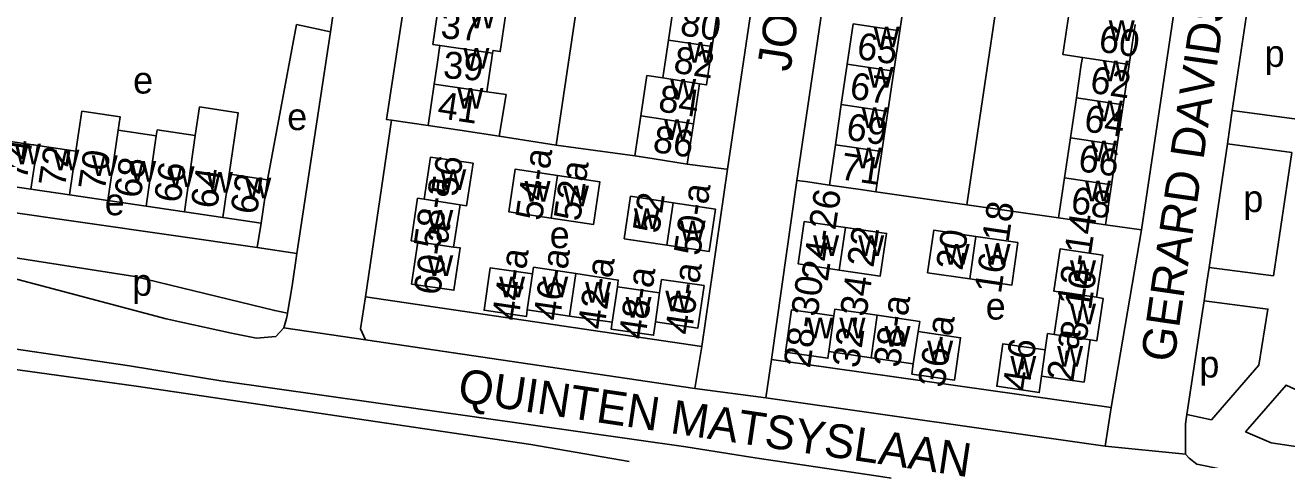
# Model space of a CAD drawing. Extents: x 163012 to 165277, y 382513 to 383987.
# Drawn here: x 163733.4 to 163920.9, y 382941.3 to 383005.9 of the extents above; entities that cross this region are included whole.
import ezdxf

# ---------------------------------------------------------------- set-up
doc = ezdxf.new("R2010")
doc.units = 0
for name, color, linetype in [('BLT_Basislijn', 7, 'Continuous'), ('BLT_Bebouwing', 7, 'Continuous'), ('BLT_Centroide', 7, 'Continuous'), ('BLT_Huisnummer', 7, 'Continuous'), ('BLT_Huisnummer_ tussenligend', 7, 'Continuous'), ('BLT_Huisnummer_reeks', 7, 'Continuous'), ('BLT_Onderverdeling_panden', 7, 'Continuous'), ('BLT_Straatnaam', 7, 'Continuous'), ('BLT_Vlakafsluiter', 7, 'Continuous')]:
    doc.layers.add(name, color=color, linetype=linetype)

msp = doc.modelspace()

# ---------------------------------------------------------------- linework, layer by layer
at = {"layer": 'BLT_Basislijn'}
for p, q in [((163769.45, 382982.9), (163773.76, 383005.95)), ((163773.76, 383005.95), (163778.82, 383004.9)), ((163773.8, 382971.94), (163778.82, 383004.9)), ((163912.83, 382993.19), (163922.44, 382991.91)), ((163787.87, 382991.74), (163783.98, 382965.47)), ((163793.29, 382990.97), (163787.87, 382991.74)), ((163812.36, 382988.05), (163803.88, 382989.36)), ((163912.1, 382988.25), (163921.69, 382986.96)), ((163824.01, 382986.42), (163812.36, 382988.05)), ((163837.27, 382984.52), (163831.82, 382985.23)), ((163837.81, 382984.44), (163833.99, 382958.09)), ((163844.33, 382956.18), (163848.1, 382982.79)), ((163852.97, 382982.1), (163849.41, 382982.61)), ((163873.4, 382979.16), (163859.87, 382981.08)), ((163887.01, 382977.21), (163873.4, 382979.16)), ((163728.05, 382978.52), (163767.9, 382972.83)), ((163767.9, 382972.83), (163768.5, 382976.45)), ((163899.33, 382975.42), (163893.98, 382976.17)), ((163894.85, 382949.03), (163899.33, 382975.42)), ((163767.9, 382972.83), (163773.8, 382971.94)), ((163773.1, 382967.11), (163773.8, 382971.94)), ((163783.98, 382965.47), (163833.99, 382958.09)), ((163908.32, 382962.66), (163906.07, 382948.01)), ((163783.99, 382959.1), (163832.93, 382951.88)), ((163832.93, 382951.88), (163833.99, 382958.09)), ((163844.33, 382956.18), (163843.49, 382950.45)), ((163844.33, 382956.18), (163894.85, 382949.03)), ((163762.51, 382952.99), (163831.62, 382943.18)), ((163843.49, 382950.45), (163893.93, 382943.26))]:
    msp.add_line(p, q, dxfattribs=at)
for points in [[(163788.12, 383067.75), (163788.07, 383067.4), (163778.82, 383004.9)], [(163848.86, 383058.88), (163837.81, 382984.44)], [(163787.87, 382991.74), (163787.1, 382991.85), (163795.88, 383049.14), (163795.92, 383049.43)], [(163910.31, 383048.96), (163910.2, 383048.25), (163899.33, 382975.42)], [(163812.36, 382988.05), (163820.82, 383045.09), (163820.88, 383045.5)], [(163848.1, 382982.79), (163855.33, 383031.73), (163855.5, 383032.85)], [(163880.83, 383029.32), (163880.66, 383028.19), (163873.4, 382979.16)], [(163915.17, 383009.03), (163912.83, 382993.19)], [(163912.83, 382993.19), (163912.1, 382988.25)], [(163912.1, 382988.25), (163909.38, 382969.84)], [(163921.69, 382986.96), (163918.94, 382968.59)], [(163837.81, 382984.44), (163837.27, 382984.52)], [(163849.41, 382982.61), (163848.1, 382982.79)], [(163772.42, 382963.06), (163770.5, 382963.43), (163749.69, 382968.5), (163729.4, 382971.68), (163728.79, 382971.24), (163728.38, 382969.07)], [(163909.38, 382969.84), (163909.06, 382967.67)], [(163909.38, 382969.84), (163918.94, 382968.59)], [(163754.38, 382962.23), (163739.99, 382966.02), (163728.92, 382968.95), (163728.38, 382969.07)], [(163909.06, 382967.67), (163908.65, 382964.89)], [(163772.42, 382963.06), (163773.1, 382967.11)], [(163783.98, 382965.47), (163783.27, 382960.75), (163783.99, 382959.1)], [(163908.65, 382964.89), (163908.32, 382962.66)], [(163908.65, 382964.89), (163918.14, 382963.65), (163916.78, 382955.31)], [(163754.38, 382962.23), (163764.09, 382960.07), (163767.78, 382959.35)], [(163767.78, 382959.35), (163770.66, 382959.57), (163771.84, 382960.86), (163772.28, 382962.24), (163772.36, 382962.72), (163772.42, 382963.06)], [(163709.47, 382952.17), (163709.84, 382953.93), (163710.03, 382954.74), (163710.48, 382955.7), (163711.05, 382956.5), (163711.99, 382957.35), (163713.32, 382958.03), (163714.74, 382958.61), (163716.43, 382959.04), (163718.05, 382959.31), (163721.95, 382959.17), (163748.93, 382955.25), (163762.51, 382952.99)], [(163703.62, 382829.62), (163715.3, 382907.82), (163715.86, 382924.36), (163716.41, 382929), (163717.21, 382932.64), (163717.47, 382936.2), (163717.23, 382939.86), (163716.47, 382943.53), (163715.71, 382947.3), (163716.39, 382948.99), (163718.15, 382950.51), (163719.84, 382952.44), (163721.19, 382954.28), (163722.24, 382956.02), (163749.89, 382952.18), (163808.55, 382943.55), (163823.2, 382940.98)], [(163916.78, 382955.31), (163909.76, 382947.2)], [(163968.8, 382943), (163956.77, 382943.99), (163943.83, 382945.66), (163933.59, 382947.74), (163922.89, 382951.43), (163920.84, 382952.36), (163914.82, 382945.41)], [(163893.93, 382943.26), (163894.85, 382949.03)], [(163905.86, 382945.2), (163905.86, 382946.61), (163906.07, 382948.01)], [(163906.07, 382948.01), (163909.76, 382947.2)], [(163905.9, 382942.08), (163905.86, 382945.2)], [(163914.82, 382945.41), (163918.6, 382943.79)], [(163831.62, 382943.18), (163841.26, 382941.65), (163842.56, 382941.46)], [(163918.6, 382943.79), (163957.28, 382937.97)], [(163842.56, 382941.46), (163860.91, 382938.73), (163862.14, 382938.55)], [(163911.24, 382939.84), (163907.55, 382940.63), (163906.43, 382941.52), (163905.9, 382942.08)]]:
    msp.add_lwpolyline(points, dxfattribs=at)
at = {"layer": 'BLT_Bebouwing'}
for p, q in [((163863.42, 383005.03), (163864.3, 383011.02)), ((163829.02, 383003.65), (163829.87, 383009.33)), ((163835.54, 383002.68), (163836.38, 383008.36)), ((163855.6, 383000.07), (163856.47, 383006.06)), ((163897.5, 383000.01), (163898.39, 383005.96)), ((163855.6, 383000.07), (163854.72, 382994.07)), ((163897.5, 383000.01), (163896.62, 382994.05)), ((163862.54, 382999.04), (163861.65, 382993.05)), ((163794.2, 382997.1), (163793.29, 382990.97)), ((163833.63, 382997.15), (163832.73, 382991.21)), ((163854.72, 382994.07), (163853.85, 382988.08)), ((163889.67, 382995.08), (163888.78, 382989.13)), ((163896.62, 382994.05), (163895.74, 382988.09)), ((163824.01, 382986.42), (163824.92, 382992.4)), ((163861.65, 382993.05), (163860.76, 382987.07)), ((163752.91, 382989.4), (163747.25, 382990.24)), ((163832.73, 382991.21), (163831.82, 382985.23)), ((163853.85, 382988.08), (163852.97, 382982.1)), ((163888.78, 382989.13), (163887.9, 382983.17)), ((163895.74, 382988.09), (163894.86, 382982.14)), ((163740.94, 382987.13), (163735.24, 382987.97)), ((163860.76, 382987.07), (163859.87, 382981.08)), ((163769.45, 382982.9), (163768.5, 382976.45)), ((163887.9, 382983.17), (163887.01, 382977.21)), ((163734.28, 382981.5), (163728.53, 382982.35)), ((163739.99, 382980.66), (163734.28, 382981.5)), ((163745.69, 382979.82), (163739.99, 382980.66)), ((163894.86, 382982.14), (163893.98, 382976.17)), ((163751.39, 382978.98), (163745.69, 382979.82)), ((163757.1, 382978.14), (163751.39, 382978.98)), ((163797.1, 382972.89), (163798.05, 382979.17)), ((163762.8, 382977.29), (163757.1, 382978.14)), ((163768.5, 382976.45), (163762.8, 382977.29)), ((163827.72, 382966.07), (163821.43, 382966.98)), ((163887.31, 382966.17), (163886.38, 382959.89)), ((163808.05, 382963.53), (163814.34, 382962.61)), ((163814.34, 382962.61), (163820.64, 382961.7)), ((163852.88, 382957.34), (163859.15, 382956.43)), ((163859.15, 382956.43), (163865.41, 382955.52))]:
    msp.add_line(p, q, dxfattribs=at)
for points in [[(163795.06, 383002.87), (163794.71, 383002.92), (163794.03, 383003.02), (163794.92, 383009.08)], [(163802.89, 383001.71), (163802.95, 383002.11), (163804.03, 383001.95), (163804.87, 383007.6)], [(163890.55, 383001.04), (163887.67, 383001.52), (163888.53, 383007.44)], [(163863.42, 383005.03), (163862.69, 383000), (163862.54, 382999.04)], [(163828.17, 382998.02), (163828.47, 383000), (163829.02, 383003.65)], [(163795.06, 383002.87), (163794.63, 383000), (163794.2, 382997.1)], [(163802.89, 383001.71), (163802.67, 383000.25), (163802.64, 383000), (163802.04, 382995.94)], [(163835.54, 383002.68), (163835.14, 383000), (163834.69, 382996.99), (163833.63, 382997.15)], [(163890.55, 383001.04), (163890.39, 383000), (163889.67, 382995.08)], [(163824.92, 382992.4), (163825.83, 382998.37), (163828.17, 382998.02)], [(163803.88, 382989.36), (163804.9, 382995.55), (163802.04, 382995.94)], [(163763.75, 382983.74), (163765.07, 382992.86), (163759.33, 382993.72), (163758.7, 382989.46)], [(163747.25, 382990.24), (163747.55, 382992.22), (163741.84, 382993.07), (163740.94, 382987.13)], [(163752.91, 382989.4), (163753.05, 382990.3), (163758.7, 382989.46)], [(163793.29, 382990.97), (163798.03, 382990.25), (163803.88, 382989.36)], [(163729.51, 382988.8), (163734.53, 382988.08), (163734.68, 382988.06), (163735.24, 382987.97)], [(163798.05, 382979.17), (163799.03, 382979.02), (163799.98, 382985.33), (163793.68, 382986.27), (163792.74, 382979.99)], [(163831.82, 382985.23), (163826.88, 382985.98), (163824.01, 382986.42)], [(163812.54, 382983.51), (163806.24, 382984.45), (163805.29, 382978.14), (163811.6, 382977.19)], [(163769.45, 382982.9), (163764.51, 382983.63), (163763.75, 382983.74)], [(163811.6, 382977.19), (163817.9, 382976.25), (163818.84, 382982.56), (163812.54, 382983.51)], [(163852.97, 382982.1), (163857.92, 382981.37), (163859.87, 382981.08)], [(163792.74, 382979.99), (163791.75, 382980.13), (163790.78, 382973.81), (163791.76, 382973.66)], [(163829.71, 382979.48), (163823.41, 382980.43), (163822.46, 382974.12), (163828.77, 382973.18)], [(163828.77, 382973.18), (163835.08, 382972.24), (163836.02, 382978.53), (163829.71, 382979.48)], [(163887.01, 382977.21), (163889.03, 382976.91), (163893.98, 382976.17)], [(163855.35, 382975.78), (163849.22, 382976.66), (163848.31, 382970.37), (163854.41, 382969.46)], [(163854.41, 382969.46), (163860.52, 382968.56), (163861.45, 382974.9), (163855.35, 382975.78)], [(163874.72, 382974.45), (163868.47, 382975.37), (163867.54, 382969.06), (163873.81, 382968.15)], [(163791.76, 382973.66), (163790.85, 382967.37), (163797.14, 382966.45), (163798.09, 382972.75), (163797.1, 382972.89)], [(163873.81, 382968.15), (163880.07, 382967.24), (163880.97, 382973.54), (163874.72, 382974.45)], [(163892.65, 382965.41), (163893.57, 382971.69), (163887.26, 382972.62), (163886.32, 382966.31), (163887.31, 382966.17)], [(163808.84, 382968.89), (163802.53, 382969.79), (163801.63, 382963.48), (163807.92, 382962.55), (163808.05, 382963.53)], [(163815.26, 382968.93), (163808.98, 382969.87), (163808.84, 382968.89)], [(163821.43, 382966.98), (163821.57, 382967.98), (163815.26, 382968.93)], [(163827.1, 382961.77), (163833.4, 382960.83), (163834.32, 382967.15), (163828.01, 382968.06), (163827.72, 382966.07)], [(163891.73, 382959.1), (163892.72, 382958.96), (163893.63, 382965.26), (163892.65, 382965.41)], [(163853.63, 382962.65), (163847.34, 382963.57), (163846.42, 382957.28), (163852.73, 382956.35), (163852.88, 382957.34)], [(163860.06, 382962.74), (163853.77, 382963.65), (163853.63, 382962.65)], [(163866.15, 382960.32), (163866.37, 382961.83), (163860.06, 382962.74)], [(163820.64, 382961.7), (163820.5, 382960.69), (163826.81, 382959.78), (163827.1, 382961.77)], [(163866.15, 382960.32), (163872.44, 382959.41), (163871.52, 382953.09), (163865.21, 382954), (163865.41, 382955.52)], [(163886.38, 382959.89), (163885.39, 382960.03), (163885.04, 382957.58)], [(163885.04, 382957.58), (163878.72, 382958.48), (163877.82, 382952.18), (163884.14, 382951.26), (163884.49, 382953.71)], [(163884.49, 382953.71), (163890.8, 382952.8), (163891.73, 382959.1)]]:
    msp.add_lwpolyline(points, dxfattribs=at)
at = {"layer": 'BLT_Onderverdeling_panden'}
for p, q in [((163863.42, 383005.03), (163856.47, 383006.06)), ((163835.54, 383002.68), (163829.02, 383003.65)), ((163795.06, 383002.87), (163802.89, 383001.71)), ((163862.54, 382999.04), (163855.6, 383000.07)), ((163890.55, 383001.04), (163897.5, 383000.01)), ((163828.17, 382998.02), (163833.63, 382997.15)), ((163802.04, 382995.94), (163794.2, 382997.1)), ((163861.65, 382993.05), (163854.72, 382994.07)), ((163889.67, 382995.08), (163896.62, 382994.05)), ((163824.92, 382992.4), (163832.73, 382991.21)), ((163745.69, 382979.82), (163747.25, 382990.24)), ((163751.39, 382978.98), (163752.91, 382989.4)), ((163757.1, 382978.14), (163758.7, 382989.46)), ((163860.76, 382987.07), (163853.85, 382988.08)), ((163888.78, 382989.13), (163895.74, 382988.09)), ((163734.28, 382981.5), (163735.24, 382987.97)), ((163739.99, 382980.66), (163740.94, 382987.13)), ((163762.8, 382977.29), (163763.75, 382983.74)), ((163811.6, 382977.19), (163812.54, 382983.51)), ((163887.9, 382983.17), (163894.86, 382982.14)), ((163792.74, 382979.99), (163798.05, 382979.17)), ((163829.71, 382979.48), (163828.77, 382973.18)), ((163854.41, 382969.46), (163855.35, 382975.78)), ((163791.76, 382973.66), (163797.1, 382972.89)), ((163874.72, 382974.45), (163873.81, 382968.15)), ((163808.84, 382968.89), (163808.05, 382963.53)), ((163814.34, 382962.61), (163815.26, 382968.93)), ((163821.43, 382966.98), (163820.64, 382961.7)), ((163827.1, 382961.77), (163827.72, 382966.07)), ((163887.31, 382966.17), (163892.65, 382965.41)), ((163853.63, 382962.65), (163852.88, 382957.34)), ((163859.15, 382956.43), (163860.06, 382962.74)), ((163866.15, 382960.32), (163865.41, 382955.52)), ((163886.38, 382959.89), (163891.73, 382959.1)), ((163885.04, 382957.58), (163884.49, 382953.71))]:
    msp.add_line(p, q, dxfattribs=at)
at = {"layer": 'BLT_Vlakafsluiter'}
for p, q in [((163783.99, 382959.1), (163771.84, 382960.86)), ((163832.93, 382951.88), (163843.49, 382950.45)), ((163893.93, 382943.26), (163905.9, 382942.08))]:
    msp.add_line(p, q, dxfattribs=at)

# ---------------------------------------------------------------- texts
at = {"layer": 'BLT_Centroide'}
for s, p in [('w', (163799.46, 383005.41)), ('w', (163859.52, 383002.56)), ('w', (163894.47, 383003.5)), ('w', (163831.85, 383000.31)), ('w', (163798.55, 382999.41)), ('p', (163917.64, 382999.67)), ('w', (163858.63, 382996.56)), ('w', (163893.59, 382997.53)), ('e', (163749.46, 382995.7)), ('w', (163829.28, 382994.78)), ('w', (163797.66, 382993.44)), ('w', (163892.7, 382991.59)), ('e', (163772.36, 382990.27)), ('w', (163828.37, 382988.81)), ('w', (163857.75, 382990.56)), ('w', (163731.89, 382985.16)), ('w', (163891.82, 382985.62)), ('w', (163737.61, 382984.31)), ('w', (163743.31, 382983.47)), ('w', (163856.87, 382984.59)), ('w', (163749.02, 382982.62)), ('w', (163754.72, 382981.8)), ('w', (163795.11, 382981.38)), ('w', (163760.42, 382980.95)), ('w', (163766.12, 382980.11)), ('w', (163807.64, 382979.64)), ('w', (163890.94, 382979.66)), ('e', (163745.24, 382977.61)), ('w', (163813.35, 382978.95)), ('p', (163914.47, 382978.09)), ('w', (163793.18, 382975.32)), ('w', (163823.89, 382975.56)), ('e', (163811.38, 382972.72)), ('w', (163830.7, 382973.72)), ('w', (163850.53, 382971.56)), ('w', (163857.23, 382971.56)), ('w', (163869.93, 382970.25)), ('w', (163876.01, 382970.25)), ('w', (163793.18, 382968.6)), ('w', (163888.71, 382967.82)), ('p', (163749.32, 382965.64)), ('w', (163803.86, 382965.42)), ('w', (163810.27, 382965.42)), ('w', (163816.64, 382964.63)), ('w', (163828.56, 382963.33)), ('w', (163822.65, 382962.39)), ('e', (163876.18, 382962.1)), ('w', (163888.71, 382961.38)), ('w', (163849.66, 382959.29)), ('w', (163854.44, 382959.29)), ('w', (163861.14, 382958.07)), ('w', (163867.49, 382955.9)), ('w', (163886.8, 382955.11)), ('w', (163879.84, 382953.64)), ('p', (163907.94, 382953.49))]:
    msp.add_text(s, height=4, dxfattribs=at).set_placement(p)
at = {"layer": 'BLT_Huisnummer'}
for s, rotation, p in [('65', 351.6267, (163856.88, 383000.88)), ('82', 351.5466, (163829.64, 382998.82)), ('62', 351.5659, (163891.55, 382995.85)), ('41', 351.3621, (163794.55, 382992.1)), ('86', 351.35, (163826.56, 382987.05)), ('74', 81.5997, (163733.65, 382982.72)), ('70', 81.5946, (163745.23, 382981.12)), ('56', 81.5978, (163797.65, 382980.28)), ('71', 351.5588, (163854.41, 382982.98)), ('66', 81.6017, (163756.48, 382979.32)), ('52a', 81.5978, (163815.89, 382976.6)), ('62', 81.5978, (163767.85, 382977.59)), ('52', 81.5978, (163827.64, 382974.79)), ('68', 351.5571, (163888.68, 382977.96)), ('22', 81.5978, (163859.49, 382969.73)), ('20', 81.5978, (163872.71, 382969.29))]:
    msp.add_text(s, height=4, rotation=rotation, dxfattribs=at).set_placement(p)
at = {"layer": 'BLT_Huisnummer_ tussenligend'}
for s, rotation, p in [('37', 355.8066, (163795.09, 383003.93)), ('80', 351.5421, (163830.61, 383004.4)), ('60', 351.5623, (163892.83, 383001.96)), ('39', 355.8066, (163795.45, 382998.01)), ('67', 351.6267, (163855.82, 382994.96)), ('84', 351.5466, (163827.37, 382993.08)), ('64', 351.5659, (163890.66, 382990.11)), ('69', 351.6267, (163855.31, 382988.87)), ('66', 351.5659, (163889.79, 382984.2)), ('72', 81.5946, (163739.32, 382981.66)), ('68', 81.6017, (163750.57, 382980.02)), ('64', 81.5978, (163761.93, 382978.45))]:
    msp.add_text(s, height=4, rotation=rotation, dxfattribs=at).set_placement(p)
at = {"layer": 'BLT_Huisnummer_reeks'}
for s, p in [('54-a', (163810.21, 382976.68)), ('58-a', (163795.07, 382972.49)), ('50-a', (163833.73, 382971.47)), ('24-26', (163852.7, 382967.65)), ('16-18', (163878.44, 382965.84)), ('12-14', (163890.69, 382963.99)), ('60-a', (163795.07, 382965.59)), ('44-a', (163806.7, 382961.8)), ('46-a', (163812.86, 382961.8)), ('42-a', (163819.47, 382960.49)), ('48-a', (163825.55, 382959.02)), ('40-a', (163832.44, 382959.7)), ('8-10', (163891.13, 382958.69)), ('28-30', (163850.05, 382954.78)), ('32-34', (163857.31, 382954.78)), ('38-a', (163863.42, 382954.85)), ('36-a', (163870.03, 382951.88)), ('2-a', (163889.19, 382952.77)), ('4-6', (163882.6, 382951.31))]:
    msp.add_text(s, height=4, rotation=81.5978, dxfattribs=at).set_placement(p)
at = {"layer": 'BLT_Straatnaam'}
for s, height, rotation, p in [('JOHANNES VERMEERSTRAAT', 5, 81.3957, (163847.12, 382998.83)), ('GERARD DAVIDSTRAAT', 4.9999, 81.7581, (163904.17, 382955.61)), ('QUINTEN MATSYSLAAN', 5, 351.5769, (163797.55, 382949.93))]:
    msp.add_text(s, height=height, rotation=rotation, dxfattribs=at).set_placement(p)

doc.saveas('drawing.dxf')
